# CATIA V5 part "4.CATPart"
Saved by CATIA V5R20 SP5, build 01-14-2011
Part number: 4
Bounding box of the stored display mesh (mm): x -75 to 5, y -2.5 to 7.5, z -5 to 5
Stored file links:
  E:\IAO_2010\iao\IAO_MMS_Groupe2\IAO_MMS_Groupe2\melguidj\Catia\4.CATPart
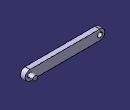
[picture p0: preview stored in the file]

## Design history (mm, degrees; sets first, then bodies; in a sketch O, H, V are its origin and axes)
Parameters
  EB4 = 70 mm
Body1 (main body)
  Sketch1 on zx-plane, origin (0, 0, 0), H (-1, 0, 0), V (0, 0, 1)
    construction line L1 (0, 0) -> (70, 0)
    line L2 (0, 5) -> (70, 5)
    line L3 (70, -5) -> (0, -5)
    arc A1 centre (70, 0) radius 5 from (70, 5) to (70, -5) cw
    arc A2 centre (0, 0) radius 5 from (0, -5) to (0, 5) cw
    circle A3 centre (70, 0) radius 2.5
    distance L1 L2 = 5
    length L1 = 70 {= EB4}
    radius A3 = 2.5
    horizontal: L1 H
    tangency: A1 L2, A2 L2, A1 L3, A2 L3
  Pad1: profile Sketch1, direction (0, 1, 0), length 2.5, mirrored extent
  Sketch2 on end face of Pad1, origin (0, 2.5, 0), H (-1, 0, 0), V (0, 0, 1)
    circle A1 centre (0, 0) radius 2.5
    radius A1 = 2.5
  Pad2: profile Sketch2, direction (0, 1, 0), length 5
  DatumSurface1
  Sketch3 on start face of Pad1, origin (0, -2.5, 0), H (1, 0, 0), V (0, 0, 1)
    point P1 (-70, 0)
    reference projected arc E1 centre (-70, 0) radius 5 from (-70, 5) to (-70, -5) ccw from edge [start face of Pad1 | face of Pad1 from Sketch1.A1]
    concentricity: P1 E1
